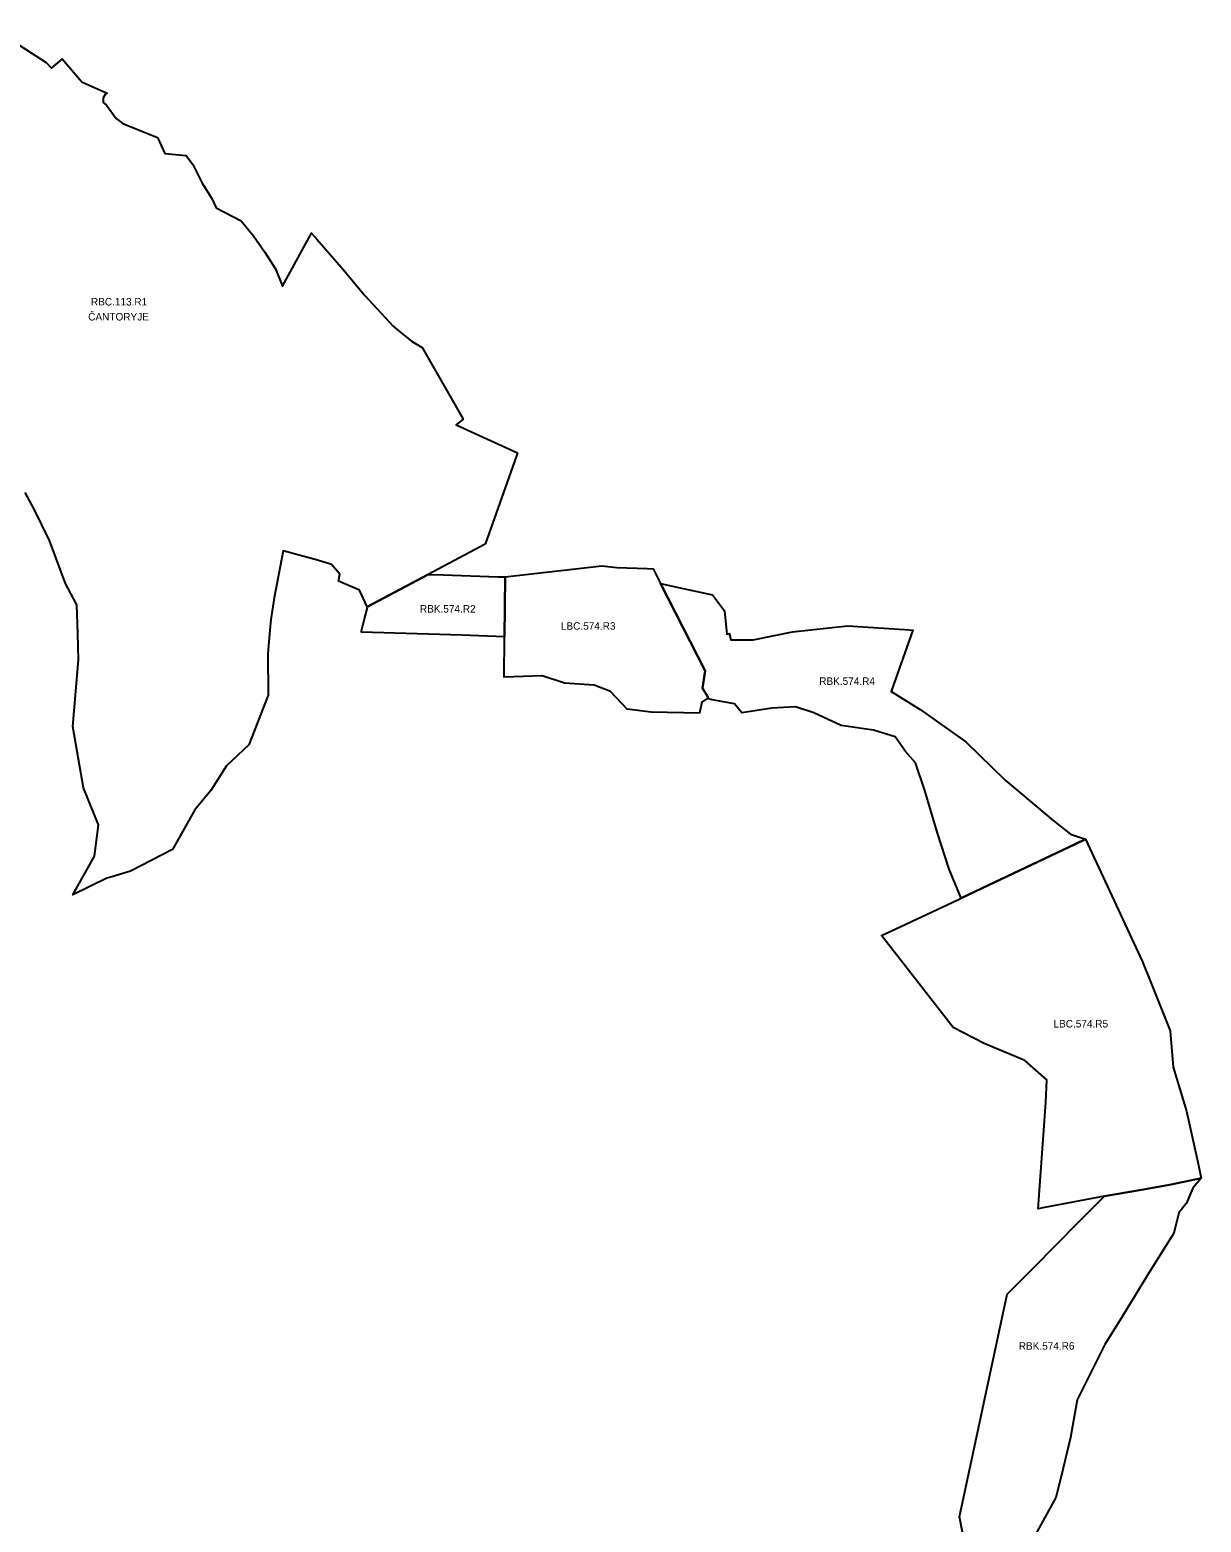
# Model space of a CAD drawing. Extents: x -450188 to -432919, y -1130252 to -1121189.
# Drawn here: x -435847 to -434285, y -1123464 to -1121474 of the extents above; entities that cross this region are included whole.
import ezdxf

# ---------------------------------------------------------------- set-up
doc = ezdxf.new("R2010")
doc.units = 0
for name, color, linetype in [('Vrstva 30', 7, 'Continuous'), ('Vrstva 31', 7, 'Continuous'), ('Vrstva 32', 7, 'Continuous'), ('Vrstva 36', 7, 'Continuous')]:
    doc.layers.add(name, color=color, linetype=linetype)

msp = doc.modelspace()

# ---------------------------------------------------------------- linework, layer by layer
at = {"layer": 'Vrstva 30'}
for p, q in [((-435239.3, -1122159.8), (-435315.3, -1122200.1)), ((-435315.3, -1122200.1), (-435396.7, -1122243.2))]:
    msp.add_line(p, q, dxfattribs=at)
for points in [[(-435892.7, -1121473.7), (-435824.6, -1121517.5), (-435817.5, -1121524.7), (-435803.5, -1121512.7), (-435803.3, -1121512.5), (-435777.3, -1121543.2), (-435775.6, -1121543.9), (-435743.3, -1121558.1), (-435745.9, -1121559.9), (-435748.6, -1121564.2), (-435748.9, -1121570.6), (-435746.8, -1121572.2), (-435744.2, -1121574.2), (-435731.4, -1121591.9), (-435722.6, -1121598.7), (-435676.2, -1121617.5), (-435666.7, -1121638.5), (-435638.3, -1121641.4), (-435629.4, -1121653.2), (-435616.9, -1121678.4), (-435603.8, -1121698.6), (-435597.9, -1121711.3), (-435564.8, -1121728.6), (-435548.1, -1121748.5), (-435533.2, -1121770.1), (-435518.9, -1121792.4), (-435509.5, -1121815.7), (-435471.1, -1121744.9), (-435463.7, -1121752.8), (-435428.2, -1121793.9), (-435399.8, -1121828.2), (-435361.9, -1121869), (-435353.6, -1121876), (-435337.5, -1121889), (-435323.4, -1121897.6), (-435268.7, -1121992.8), (-435278.1, -1122000.7), (-435196.2, -1122038), (-435200.2, -1122049.6), (-435239.3, -1122159.8)], [(-435396.7, -1122243.2), (-435406.8, -1122221.3), (-435435, -1122209.2), (-435433.2, -1122199.6), (-435444.3, -1122186.8), (-435463.1, -1122181), (-435508.7, -1122168.7), (-435520.6, -1122231.2), (-435525.2, -1122260.2), (-435526.6, -1122274.4), (-435529.4, -1122305.7), (-435528.8, -1122361.1), (-435554.4, -1122427.3), (-435584.5, -1122455.2), (-435605.3, -1122488.1), (-435626.7, -1122514.2), (-435656.4, -1122566.8), (-435712.5, -1122595.9), (-435737.3, -1122603.5), (-435743.8, -1122605.4), (-435789.3, -1122627.6), (-435760.2, -1122575.9), (-435754.9, -1122534.2), (-435775, -1122484.7), (-435781.6, -1122446.7), (-435789.1, -1122403.1), (-435781.5, -1122313.8), (-435782.5, -1122278.9), (-435784.1, -1122240.7), (-435788, -1122233.2), (-435798.9, -1122212.4), (-435820.2, -1122154.7), (-435840.6, -1122113.1), (-435852.8, -1122090.7)]]:
    msp.add_lwpolyline(points, dxfattribs=at)
at = {"layer": 'Vrstva 31'}
for p, q in [((-434946, -1122328.8), (-435005.4, -1122212.3)), ((-435396.7, -1122243.2), (-435396.7, -1122243.2)), ((-435404.9, -1122277.1), (-435400.4, -1122259.5)), ((-435374.3, -1122278), (-435404.9, -1122277.1)), ((-435270.6, -1122281.1), (-435374.3, -1122278)), ((-435213.4, -1122283.3), (-435270.6, -1122281.1)), ((-435213.4, -1122283.3), (-435213.4, -1122283.3)), ((-434943.2, -1122365.4), (-434941.8, -1122364.4)), ((-434413.4, -1123029.2), (-434363.9, -1123020.8))]:
    msp.add_line(p, q, dxfattribs=at)
for points in [[(-435396.7, -1122243.2), (-435315.3, -1122200.1), (-435294.8, -1122200.8), (-435222.6, -1122203.2), (-435212.6, -1122203.5), (-435213.4, -1122283.3)], [(-435005.4, -1122212.3), (-434981.6, -1122217.5), (-434936, -1122227.5), (-434920.2, -1122248.5), (-434917.3, -1122279.9), (-434914.2, -1122278.9), (-434911.6, -1122287.3), (-434881.8, -1122287.3), (-434829.6, -1122276.7), (-434756.1, -1122268.8), (-434680.1, -1122273.4), (-434669.2, -1122274.3), (-434698.1, -1122356.1), (-434659.1, -1122380.1), (-434598.2, -1122423.4), (-434545.8, -1122474.4), (-434482, -1122528.2), (-434458.6, -1122546.6)], [(-435400.4, -1122259.5), (-435396.3, -1122244), (-435396.7, -1122243.2)], [(-434941.8, -1122364.4), (-434949.7, -1122351.7), (-434946, -1122328.8)], [(-434458.6, -1122546.6), (-434438.8, -1122553.3), (-434452.8, -1122560), (-434568.1, -1122614.5), (-434604.8, -1122631.8), (-434620.7, -1122593.2), (-434636.1, -1122545.4), (-434653, -1122488.5), (-434665.5, -1122451.3), (-434678.7, -1122436.1), (-434692.6, -1122416.9), (-434721.7, -1122407.7), (-434764.7, -1122401.7), (-434801.1, -1122384.5), (-434825.6, -1122376.6), (-434857.3, -1122378.6), (-434897, -1122384.5), (-434907, -1122372.6), (-434936.7, -1122367.3), (-434943.2, -1122365.4)], [(-434363.9, -1123020.8), (-434324.5, -1123013.7), (-434284.6, -1123005.4), (-434295.7, -1123018.7), (-434299.7, -1123028.1), (-434301.1, -1123031.3), (-434304.3, -1123038.5), (-434314.4, -1123051.7), (-434320.8, -1123078.5), (-434332, -1123096.3), (-434354, -1123131.2), (-434377.2, -1123169.1), (-434389.6, -1123189.4), (-434412.9, -1123227.4), (-434449.8, -1123301), (-434458.9, -1123351.3), (-434471.9, -1123405.2), (-434478.2, -1123431.2), (-434512.4, -1123493.4), (-434518, -1123539.7)], [(-434580.6, -1123591.5), (-434606.8, -1123457.2), (-434543.2, -1123160.2), (-434507.9, -1123124.6), (-434478.5, -1123094.9), (-434447.2, -1123063.3), (-434413.4, -1123029.2)]]:
    msp.add_lwpolyline(points, dxfattribs=at)
at = {"layer": 'Vrstva 32'}
for p, q in [((-435213.4, -1122283.3), (-435212.6, -1122203.5)), ((-435005.4, -1122212.3), (-434946, -1122328.8)), ((-434946, -1122328.8), (-434949.7, -1122351.7)), ((-434949.7, -1122351.7), (-434941.8, -1122364.4)), ((-434452.8, -1122560), (-434438.8, -1122553.3)), ((-434363.9, -1123020.8), (-434413.4, -1123029.2)), ((-434324.5, -1123013.7), (-434363.9, -1123020.8))]:
    msp.add_line(p, q, dxfattribs=at)
for points in [[(-435212.6, -1122203.5), (-435083.9, -1122188.7), (-435063.6, -1122191), (-435023.4, -1122192.2), (-435015.5, -1122192.5), (-435005.4, -1122212.3)], [(-434941.8, -1122364.4), (-434943.2, -1122365.4), (-434950.3, -1122370.5), (-434953.4, -1122385.1), (-435018.2, -1122383.6), (-435050, -1122379.6), (-435072.2, -1122356.2), (-435094, -1122347.9), (-435133.7, -1122345.1), (-435163.5, -1122335.2), (-435213.9, -1122337.2), (-435213.4, -1122283.6), (-435213.4, -1122283.3)], [(-434413.4, -1123029.2), (-434462.6, -1123038.6), (-434493.4, -1123044.5), (-434501.9, -1123046.1), (-434491.7, -1122904.5), (-434490.5, -1122874), (-434519.6, -1122848.5), (-434574.1, -1122825.8), (-434615.2, -1122804.5), (-434710.7, -1122681.8), (-434685, -1122669.8), (-434609.2, -1122633.9), (-434604.8, -1122631.8), (-434568.1, -1122614.5), (-434452.8, -1122560)], [(-434438.8, -1122553.3), (-434362.6, -1122716.9), (-434351.6, -1122744.4), (-434325.8, -1122808.8), (-434322.1, -1122857.1), (-434303.9, -1122915.8), (-434289.2, -1122983.9), (-434284.6, -1123005.4), (-434324.5, -1123013.7)]]:
    msp.add_lwpolyline(points, dxfattribs=at)

# ---------------------------------------------------------------- texts
at = {"layer": 'Vrstva 36'}
for s, p in [('RBC.113.R1', (-435765.1, -1121841.4)), ('ČANTORYJE', (-435768.7, -1121861.4)), ('RBK.574.R2', (-435326.4, -1122251)), ('LBC.574.R3', (-435138.4, -1122273.8)), ('RBK.574.R4', (-434793.9, -1122347.4)), ('LBC.574.R5', (-434481.5, -1122804.4)), ('RBK.574.R6', (-434527.8, -1123234.1))]:
    msp.add_text(s, height=10, dxfattribs=at).set_placement(p)

doc.saveas('drawing.dxf')
